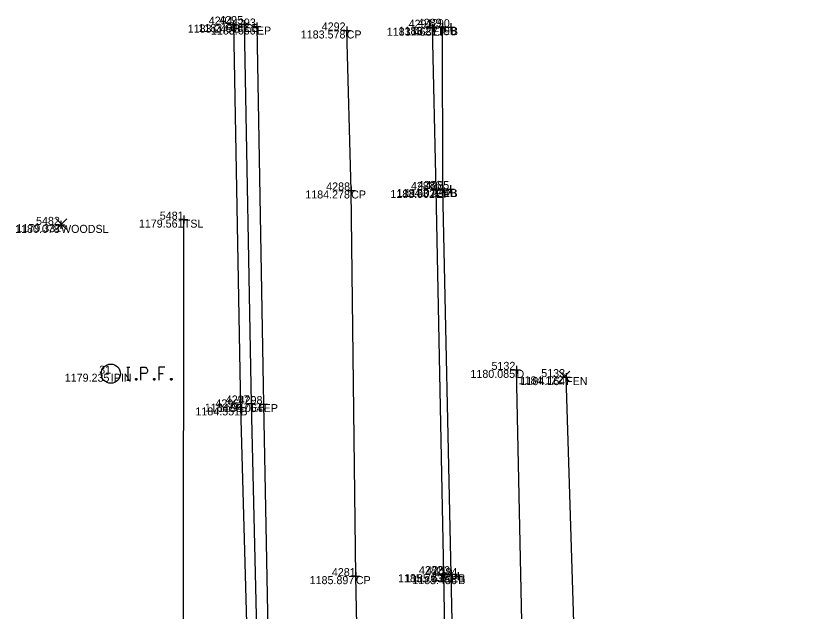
# Model space of a CAD drawing. Extents: x 2044996 to 2050343, y 455232 to 458054.
# Drawn here: x 2047569.6 to 2047669.1, y 457979.7 to 458054.1 of the extents above; entities that cross this region are included whole.
import ezdxf

# ---------------------------------------------------------------- set-up
doc = ezdxf.new("R2010")
doc.units = 0
for name, color, linetype in [('DR_X_Ditch', 7, 'Continuous'), ('DT_X_Contour_Minor', 7, 'Continuous'), ('DT_X_Contour_Text', 7, 'Continuous'), ('DT_X_Spot_Elev', 7, 'Continuous'), ('DT_X_Triangles', 7, 'Continuous'), ('DT_X_Void', 7, 'Continuous'), ('PV_X_COP', 7, 'Continuous'), ('PV_X_EOP', 7, 'Continuous'), ('PV_X_Shoulder_Aggregate', 7, 'Continuous'), ('RD_X_Fence', 7, 'Continuous'), ('SV_X_Break_Lines', 7, 'Continuous'), ('SV_X_Toe_of_Slope', 7, 'Continuous'), ('XS_X_Ground_Line', 7, 'Continuous')]:
    doc.layers.add(name, color=color, linetype=linetype)

msp = doc.modelspace()

# ---------------------------------------------------------------- linework, layer by layer
at = {"layer": 'DR_X_Ditch'}
msp.add_lwpolyline([(2047636.699, 457873.734), (2047633.739, 457933.195), (2047632.119, 458009.836)], dxfattribs=at)
at = {"layer": 'DT_X_Spot_Elev'}
for p, q in [((2047574.601, 458027.38), (2047575.934, 458028.715)), ((2047574.601, 458028.715), (2047575.934, 458027.38)), ((2047637.452, 458008.356), (2047638.785, 458009.691)), ((2047637.452, 458009.691), (2047638.785, 458008.356))]:
    msp.add_line(p, q, dxfattribs=at)
at = {"layer": 'DT_X_Void'}
for p, q in [((2047596.271, 458052.992), (2047597.271, 458052.992)), ((2047596.771, 458053.492), (2047596.771, 458052.492)), ((2047596.771, 458052.992), (2047596.771, 458052.992)), ((2047597.624, 458053.061), (2047598.624, 458053.061)), ((2047598.124, 458053.561), (2047598.124, 458052.561)), ((2047598.124, 458053.061), (2047598.124, 458053.061)), ((2047599.695, 458053.25), (2047599.695, 458052.25)), ((2047621.646, 458053.098), (2047621.646, 458052.098)), ((2047622.903, 458053.224), (2047622.903, 458052.224)), ((2047623.936, 458053.164), (2047623.936, 458052.164)), ((2047599.195, 458052.75), (2047600.195, 458052.75)), ((2047599.695, 458052.75), (2047599.695, 458052.75)), ((2047610.412, 458052.257), (2047611.412, 458052.257)), ((2047610.912, 458052.757), (2047610.912, 458051.757)), ((2047610.912, 458052.257), (2047610.912, 458052.257)), ((2047621.146, 458052.598), (2047622.146, 458052.598)), ((2047621.646, 458052.598), (2047621.646, 458052.598)), ((2047622.403, 458052.724), (2047623.403, 458052.724)), ((2047622.903, 458052.724), (2047622.903, 458052.724)), ((2047623.436, 458052.664), (2047624.436, 458052.664)), ((2047623.936, 458052.664), (2047623.936, 458052.664)), ((2047610.975, 458032.257), (2047611.975, 458032.257)), ((2047611.475, 458032.757), (2047611.475, 458031.757)), ((2047611.475, 458032.257), (2047611.475, 458032.257)), ((2047621.602, 458032.325), (2047622.602, 458032.325)), ((2047622.102, 458032.825), (2047622.102, 458031.825)), ((2047622.102, 458032.325), (2047622.102, 458032.325)), ((2047622.405, 458032.45), (2047623.405, 458032.45)), ((2047622.905, 458032.95), (2047622.905, 458031.95)), ((2047622.905, 458032.45), (2047622.905, 458032.45)), ((2047623.382, 458032.425), (2047624.382, 458032.425)), ((2047623.882, 458032.925), (2047623.882, 458031.925)), ((2047623.882, 458032.425), (2047623.882, 458032.425)), ((2047590.565, 458029.115), (2047590.565, 458028.115)), ((2047575.224, 458028.457), (2047575.224, 458027.457)), ((2047590.065, 458028.615), (2047591.065, 458028.615)), ((2047590.565, 458028.615), (2047590.565, 458028.615)), ((2047574.724, 458027.957), (2047575.724, 458027.957)), ((2047575.224, 458027.957), (2047575.224, 458027.957)), ((2047632.119, 458010.336), (2047632.119, 458009.336)), ((2047631.619, 458009.836), (2047632.619, 458009.836)), ((2047632.119, 458009.836), (2047632.119, 458009.836)), ((2047638.327, 458009.43), (2047638.327, 458008.43)), ((2047637.827, 458008.93), (2047638.827, 458008.93)), ((2047638.327, 458008.93), (2047638.327, 458008.93)), ((2047598.971, 458006.131), (2047598.971, 458005.131)), ((2047597.132, 458005.144), (2047598.132, 458005.144)), ((2047597.632, 458005.644), (2047597.632, 458004.644)), ((2047597.632, 458005.144), (2047597.632, 458005.144)), ((2047598.471, 458005.631), (2047599.471, 458005.631)), ((2047598.971, 458005.631), (2047598.971, 458005.631)), ((2047600.039, 458005.561), (2047601.039, 458005.561)), ((2047600.539, 458006.061), (2047600.539, 458005.061)), ((2047600.539, 458005.561), (2047600.539, 458005.561)), ((2047612.061, 457984.551), (2047612.061, 457983.551)), ((2047622.552, 457984.299), (2047623.552, 457984.299)), ((2047623.052, 457984.799), (2047623.052, 457983.799)), ((2047623.052, 457984.299), (2047623.052, 457984.299)), ((2047623.458, 457984.293), (2047624.458, 457984.293)), ((2047623.958, 457984.793), (2047623.958, 457983.793)), ((2047623.958, 457984.293), (2047623.958, 457984.293)), ((2047624.845, 457984.552), (2047624.845, 457983.552)), ((2047611.561, 457984.051), (2047612.561, 457984.051)), ((2047612.061, 457984.051), (2047612.061, 457984.051)), ((2047624.345, 457984.052), (2047625.345, 457984.052)), ((2047624.845, 457984.052), (2047624.845, 457984.052))]:
    msp.add_line(p, q, dxfattribs=at)
at = {"layer": 'PV_X_COP'}
msp.add_lwpolyline([(2047630.697, 457032.772), (2047629.568, 457079.465), (2047628.826, 457121.309), (2047627.827, 457168.374), (2047627.226, 457213.893), (2047626.35, 457261.407), (2047625.275, 457313.882), (2047624.137, 457367.694), (2047623.142, 457414.957), (2047622.163, 457463.478), (2047621.208, 457510.605), (2047620.335, 457561.899), (2047619.472, 457614.832), (2047618.326, 457662.229), (2047617.507, 457713.134), (2047616.391, 457759.383), (2047615.436, 457807.272), (2047614.413, 457854.523), (2047614.295, 457881.561), (2047613.156, 457931.145), (2047612.061, 457984.051), (2047611.475, 458032.257), (2047610.912, 458052.257)], dxfattribs=at)
at = {"layer": 'PV_X_EOP'}
for p, q in [((2047599.695, 458052.75), (2047600.539, 458005.561)), ((2047622.102, 458032.325), (2047621.646, 458052.598)), ((2047623.052, 457984.299), (2047622.102, 458032.325)), ((2047600.539, 458005.561), (2047601.376, 457960.282)), ((2047623.893, 457929.668), (2047623.052, 457984.299))]:
    msp.add_line(p, q, dxfattribs=at)
at = {"layer": 'PV_X_Shoulder_Aggregate'}
for p, q in [((2047598.124, 458053.061), (2047598.971, 458005.631)), ((2047598.971, 458005.631), (2047600.071, 457960.658))]:
    msp.add_line(p, q, dxfattribs=at)
msp.add_lwpolyline([(2047636.928, 457312.89), (2047635.932, 457367.469), (2047634.969, 457414.597), (2047633.924, 457462.124), (2047633.135, 457509.725), (2047632.168, 457560.257), (2047631.156, 457614.811), (2047630.46, 457661.293), (2047629.396, 457713.733), (2047628.5, 457758.086), (2047627.361, 457807.431), (2047627.483, 457822.094), (2047628.609, 457825.867), (2047628.679, 457844.065), (2047627.204, 457879.146), (2047626.259, 457880.502), (2047625.13, 457929.522), (2047623.958, 457984.293), (2047622.905, 458032.45), (2047622.903, 458052.724)], dxfattribs=at)
at = {"layer": 'RD_X_Fence'}
msp.add_lwpolyline([(2047669.053, 457872.512), (2047643.07, 457872.168), (2047640.665, 457934.297), (2047638.327, 458008.93)], dxfattribs=at)
at = {"layer": 'SV_X_Break_Lines'}
msp.add_lwpolyline([(2047596.771, 458052.992), (2047597.632, 458005.144), (2047598.886, 457960.243), (2047599.592, 457916.87), (2047599.732, 457889.847)], dxfattribs=at)
at = {"layer": 'SV_X_Toe_of_Slope'}
msp.add_lwpolyline([(2047592.652, 457921.181), (2047590.547, 457975.844), (2047590.565, 458028.615)], dxfattribs=at)
at = {"layer": 'XS_X_Ground_Line'}
for points in [[(2047583.454, 458010.156), (2047583.807, 458010.156)], [(2047583.631, 458008.556), (2047583.631, 458010.156)], [(2047585.196, 458008.556), (2047585.196, 458010.156), (2047585.725, 458010.156), (2047585.78, 458010.144), (2047585.857, 458010.118), (2047585.891, 458010.093), (2047585.924, 458010.068), (2047585.968, 458010.005), (2047586.001, 458009.942), (2047586.023, 458009.841), (2047586.023, 458009.69), (2047586.012, 458009.64), (2047585.99, 458009.564), (2047585.946, 458009.476), (2047585.902, 458009.438), (2047585.869, 458009.413), (2047585.813, 458009.388), (2047585.725, 458009.375), (2047585.196, 458009.375)], [(2047588.205, 458010.156), (2047587.445, 458010.156), (2047587.445, 458008.556)], [(2047587.445, 458009.375), (2047587.985, 458009.375)], [(2047583.454, 458008.556), (2047583.807, 458008.556)], [(2047584.59, 458008.771), (2047584.645, 458008.771), (2047584.678, 458008.745), (2047584.711, 458008.695), (2047584.711, 458008.632), (2047584.678, 458008.581), (2047584.645, 458008.556), (2047584.59, 458008.556), (2047584.557, 458008.581), (2047584.524, 458008.632), (2047584.524, 458008.695), (2047584.557, 458008.745), (2047584.59, 458008.771)], [(2047586.839, 458008.771), (2047586.894, 458008.771), (2047586.927, 458008.745), (2047586.96, 458008.695), (2047586.96, 458008.632), (2047586.927, 458008.581), (2047586.894, 458008.556), (2047586.839, 458008.556), (2047586.805, 458008.581), (2047586.772, 458008.632), (2047586.772, 458008.695), (2047586.805, 458008.745), (2047586.839, 458008.771)], [(2047588.988, 458008.771), (2047589.043, 458008.771), (2047589.076, 458008.745), (2047589.109, 458008.695), (2047589.109, 458008.632), (2047589.076, 458008.581), (2047589.043, 458008.556), (2047588.988, 458008.556), (2047588.955, 458008.581), (2047588.922, 458008.632), (2047588.922, 458008.695), (2047588.955, 458008.745), (2047588.988, 458008.771)]]:
    msp.add_lwpolyline(points, dxfattribs=at)
msp.add_circle((2047581.44, 458009.356), 1.2, dxfattribs=at)

# ---------------------------------------------------------------- texts
at = {"layer": 'DT_X_Contour_Minor'}
for s, p in [('1183.249', (2047591.057, 458051.992)), ('1183.606', (2047592.387, 458052.061)), ('1183.666', (2047593.958, 458051.75)), ('1183.578', (2047605.18, 458051.257)), ('1183.463', (2047615.924, 458051.598)), ('1183.211', (2047617.393, 458051.724)), ('1182.779', (2047618.222, 458051.664)), ('1184.278', (2047605.743, 458031.257)), ('1183.902', (2047616.372, 458031.325)), ('1184.072', (2047617.175, 458031.45)), ('1183.234', (2047618.177, 458031.425)), ('1179.331', (2047569.654, 458027.047)), ('1179.561', (2047584.952, 458027.615)), ('1180.078', (2047569.492, 458026.957)), ('1179.235', (2047575.696, 458008.356)), ('1180.085', (2047626.375, 458008.836)), ('1184.122', (2047632.389, 458008.023)), ('1184.164', (2047632.623, 458007.93)), ('1184.551', (2047592.018, 458004.144)), ('1184.947', (2047593.195, 458004.631)), ('1185.064', (2047594.835, 458004.561)), ('1185.733', (2047617.329, 457983.299)), ('1185.635', (2047618.214, 457983.293)), ('1185.897', (2047606.286, 457983.051)), ('1185.456', (2047619.108, 457983.052))]:
    msp.add_text(s, height=1, dxfattribs=at).set_placement(p)
at = {"layer": 'DT_X_Contour_Text'}
for s, p in [('B', (2047596.771, 458051.992)), ('EB', (2047598.124, 458052.061)), ('EP', (2047599.695, 458051.75)), ('CP', (2047610.912, 458051.257)), ('EP', (2047621.646, 458051.598)), ('EB', (2047622.903, 458051.724)), ('B', (2047623.936, 458051.664)), ('CP', (2047611.475, 458031.257)), ('EP', (2047622.102, 458031.325)), ('EB', (2047622.905, 458031.45)), ('B', (2047623.882, 458031.425)), ('TSL', (2047590.565, 458027.615)), ('WOODSL', (2047575.224, 458026.957)), ('IPIN', (2047581.44, 458008.356)), ('D', (2047632.119, 458008.836)), ('FEN', (2047638.327, 458007.93)), ('B', (2047597.632, 458004.144)), ('EB', (2047598.971, 458004.631)), ('EP', (2047600.539, 458004.561)), ('EP', (2047623.052, 457983.299)), ('EB', (2047623.958, 457983.293)), ('CP', (2047612.061, 457983.051)), ('B', (2047624.845, 457983.052))]:
    msp.add_text(s, height=1, dxfattribs=at).set_placement(p)
at = {"layer": 'DT_X_Triangles'}
for s, p in [('4294', (2047593.681, 458052.992)), ('4295', (2047594.994, 458053.061)), ('4293', (2047596.587, 458052.75)), ('4292', (2047607.797, 458052.257)), ('4291', (2047618.647, 458052.598)), ('4289', (2047619.803, 458052.724)), ('4290', (2047620.816, 458052.664)), ('4288', (2047608.357, 458032.257)), ('4287', (2047618.94, 458032.325)), ('4286', (2047619.782, 458032.45)), ('4285', (2047620.752, 458032.425)), ('5481', (2047587.566, 458028.615)), ('5482', (2047572.109, 458027.957)), ('31', (2047579.994, 458009.356)), ('5132', (2047629.004, 458009.836)), ('5133', (2047635.219, 458008.93)), ('4296', (2047594.509, 458005.144)), ('4297', (2047595.809, 458005.631)), ('4298', (2047597.421, 458005.561)), ('4282', (2047619.937, 457984.299)), ('4283', (2047620.849, 457984.293)), ('4281', (2047609.062, 457984.051)), ('4284', (2047621.755, 457984.052))]:
    msp.add_text(s, height=1, dxfattribs=at).set_placement(p)

doc.saveas('drawing.dxf')
